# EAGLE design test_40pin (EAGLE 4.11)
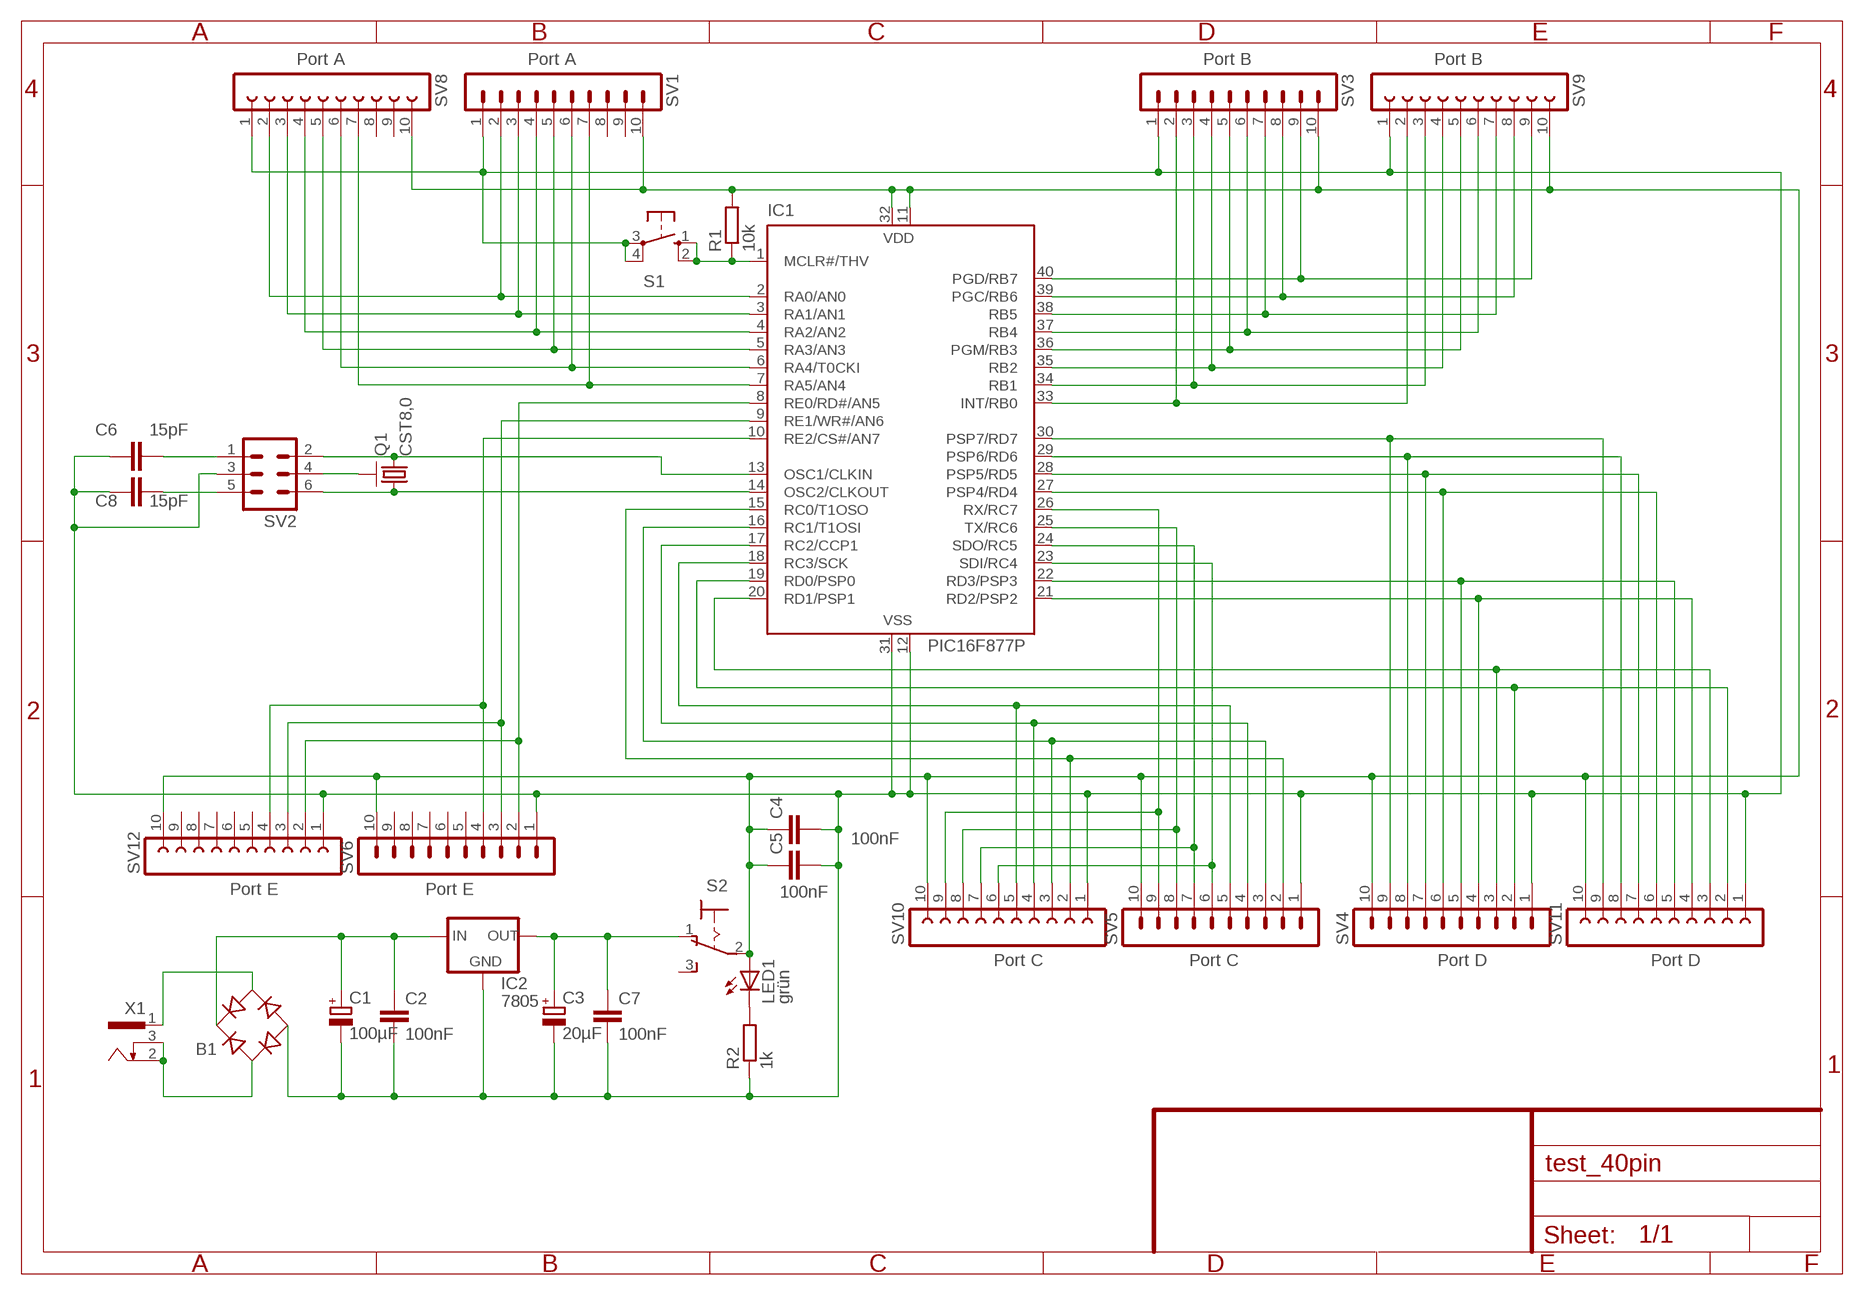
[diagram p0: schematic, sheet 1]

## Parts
B1  RB1A  [RB1A]
C1  100µF  CPOL-EUE5-10.5  [E5-10,5]
C2  100nF  C-EU050-025X075  [C050-025X075]
C3  20µF  CPOL-EUE5-5  [E5-5]
C4  100nF  C-EU050-025X075  [C050-025X075]
C5  100nF  C-EU050-025X075  [C050-025X075]
C6  15pF  C-EU025-025X050  [C025-025X050]
C7  100nF  C-EU050-025X075  [C050-025X075]
C8  15pF  C-EU025-025X050  [C025-025X050]
IC1  PIC16F877P  [DIL40]
IC2  7805  78XXS  [78XXS]
LED1  grün  LED3MM  [LED3MM]
Q1  CST8,0  RESONATOR  [RES3PIN]
R1  10k  R-EU_0207/10  [0207/10]
R2  1k  R-EU_0207/10  [0207/10]
S1  10-XX  [B3F-10XX]
S2  320-916  [320-916]
SV1  Port A  MA10-1  [MA10-1]
SV2  MA03-2  [MA03-2]
SV3  Port B  MA10-1  [MA10-1]
SV4  Port D  MA10-1  [MA10-1]
SV5  Port C  MA10-1  [MA10-1]
SV6  Port E  MA10-1  [MA10-1]
SV8  Port A  FE10W  [FE10W]
SV9  Port B  FE10W  [FE10W]
SV10  Port C  FE10W  [FE10W]
SV11  Port D  FE10W  [FE10W]
SV12  Port E  FE10W  [FE10W]
X1  733989-55  [733989-5]

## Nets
N$1: IC1.2(RA0/AN0) SV1.2 SV8.2
N$2: IC1.3(RA1/AN1) SV1.3 SV8.3
N$3: IC1.4(RA2/AN2) SV1.4 SV8.4
N$4: IC1.5(RA3/AN3) SV1.5 SV8.5
N$5: IC1.6(RA4/T0CKI) SV1.6 SV8.6
N$6: IC1.7(RA5/AN4) SV1.7 SV8.7
N$7: IC1.40(PGD/RB7) SV3.9 SV9.9
N$8: IC1.39(PGC/RB6) SV3.8 SV9.8
N$9: IC1.38(RB5) SV3.7 SV9.7
N$10: IC1.37(RB4) SV3.6 SV9.6
N$11: IC1.36(PGM/RB3) SV3.5 SV9.5
N$12: IC1.35(RB2) SV3.4 SV9.4
N$13: IC1.34(RB1) SV3.3 SV9.3
N$14: IC1.33(INT/RB0) SV3.2 SV9.2
N$15: IC1.26(RX/RC7) SV5.9 SV10.9
N$16: IC1.25(TX/RC6) SV5.8 SV10.8
N$17: IC1.24(SDO/RC5) SV5.7 SV10.7
N$18: IC1.23(SDI/RC4) SV5.6 SV10.6
N$19: IC1.18(RC3/SCK) SV5.5 SV10.5
N$20: IC1.17(RC2/CCP1) SV5.4 SV10.4
N$21: IC1.16(RC1/T1OSI) SV5.3 SV10.3
N$22: IC1.15(RC0/T1OSO) SV5.2 SV10.2
N$23: IC1.30(PSP7/RD7) SV4.9 SV11.9
N$24: IC1.29(PSP6/RD6) SV4.8 SV11.8
N$25: IC1.28(PSP5/RD5) SV4.7 SV11.7
N$26: IC1.27(PSP4/RD4) SV4.6 SV11.6
N$27: IC1.19(RD0/PSP0) SV4.2 SV11.2
N$28: IC1.20(RD1/PSP1) SV4.3 SV11.3
N$29: IC1.21(RD2/PSP2) SV4.4 SV11.4
N$30: IC1.22(RD3/PSP3) SV4.5 SV11.5
N$31: IC1.8(RE0/RD#/AN5) SV6.2 SV12.2
N$32: IC1.9(RE1/WR#/AN6) SV6.3 SV12.3
N$33: IC1.10(RE2/CS#/AN7) SV6.4 SV12.4
N$34: IC1.14(OSC2/CLKOUT) Q1.1 SV2.6
N$35: IC1.1(MCLR#/THV) R1.1 S1.1(S) S1.2(S1)
N$37: C3.+ C7.1 IC2.OUT S2.1(O)
N$38: IC1.13(OSC1/CLKIN) Q1.3 SV2.2
N$39: B1.AC1 X1.2 X1.3
N$40: Q1.2 SV2.4
N$42: B1.+ C1.+ C2.1 IC2.IN
N$43: B1.AC2 X1.1
N$44: C6.2 SV2.1
N$45: C8.2 SV2.5
N$47: LED1.K(C) R2.2
VDD: C4.1 C5.1 IC1.11(VDD) IC1.32(VDD) LED1.A R1.2 S2.2(P) SV1.10 SV3.10 SV4.10 SV5.10 SV6.10 SV8.10 SV9.10 SV10.10 SV11.10 SV12.10
VSS: B1.- C1.- C2.2 C3.- C4.2 C5.2 C6.1 C7.2 C8.1 IC1.12(VSS) IC1.31(VSS) IC2.GND R2.1 S1.3(P) S1.4(P1) SV1.1 SV2.3 SV3.1 SV4.1 SV5.1 SV6.1 SV8.1 SV9.1 SV10.1 SV11.1 SV12.1
Unconnected: S2.3(S) SV1.8 SV1.9 SV6.5 SV6.6 SV6.7 SV6.8 SV6.9 SV8.8 SV8.9 SV12.5 SV12.6 SV12.7 SV12.8 SV12.9

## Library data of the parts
B1 = rectifier:RB1A: RECTIFIER 1 A
C1 C3 = rcl:CPOL-EU: POLARIZED CAPACITOR, European symbol
C2 C4-C8 = rcl:C-EU: CAPACITOR, European symbol
IC1 = microchip:PIC16F87*: MICROCONTROLLER
IC2 = v-reg:78XXS: VOLTAGE REGULATOR
LED1 = led:LED: LED
Q1 = sprut:RESONATOR: CRYSTAL
R1 R2 = rcl:R-EU_: RESISTOR, European symbol
S1 = switch-omron:10-XX: OMRON SWITCH
S2 = switch:320-916: TOGGLE SWITCH distributor RS Components
SV1 SV3-SV6 = con-lstb:MA10-1: PIN HEADER
SV2 = con-lstb:MA03-2: PIN HEADER
SV8-SV12 = con-lsta:FE10W: FEMALE HEADER
X1 = con-conrad:733989-55: FEMALE PRINT CONNECTOR 1.1 mm, FUK HING Industries, distributor Conrad

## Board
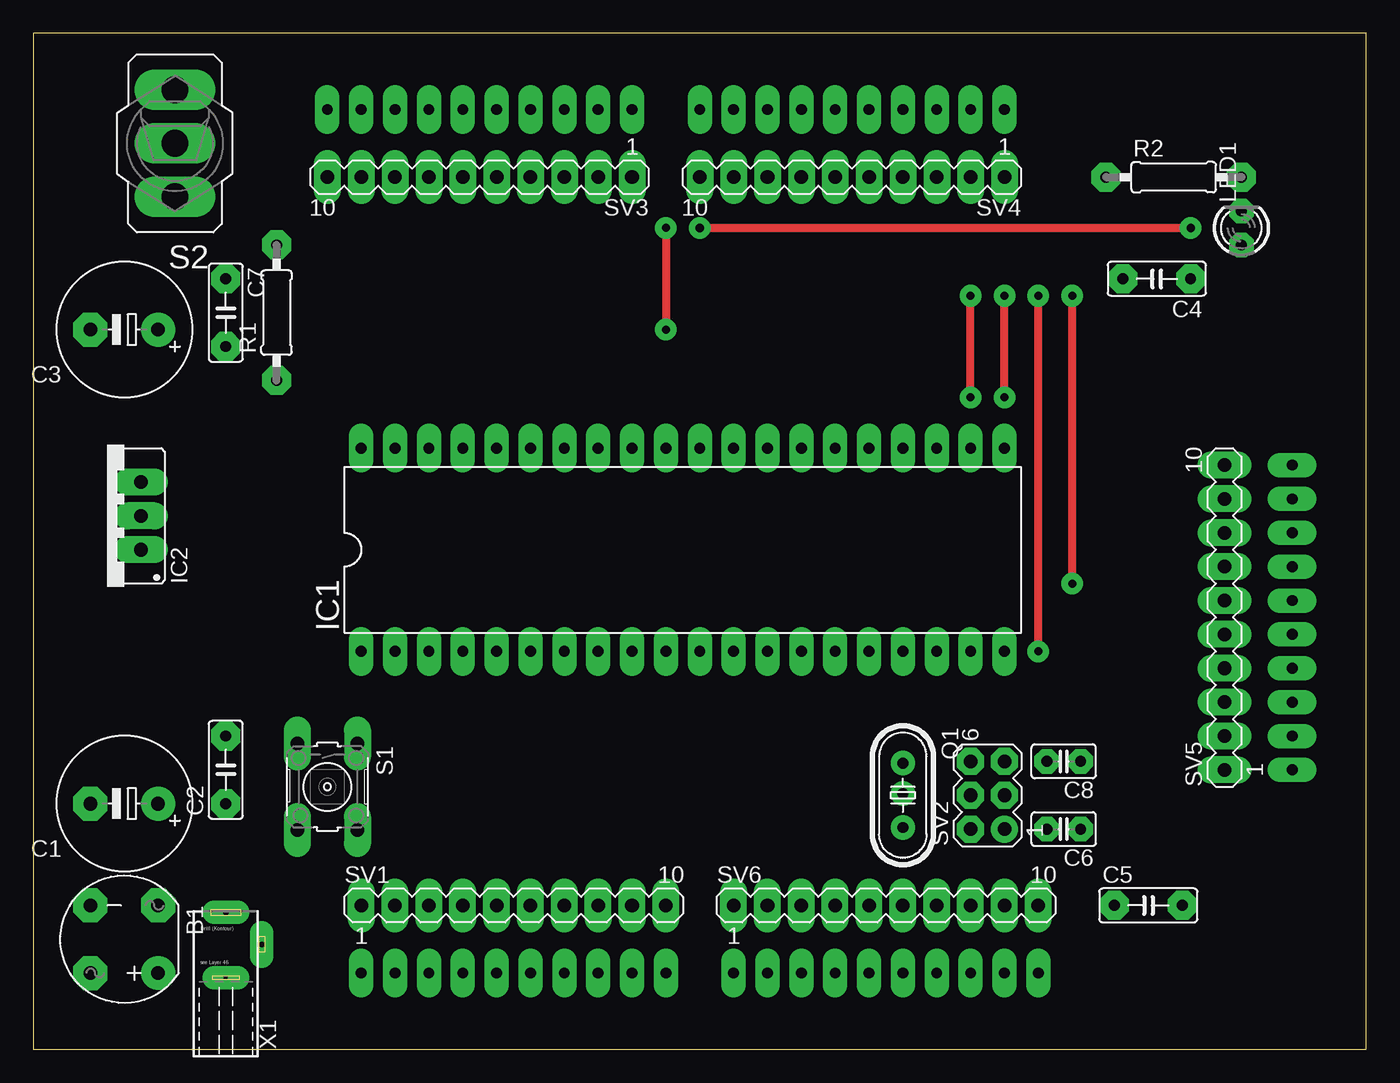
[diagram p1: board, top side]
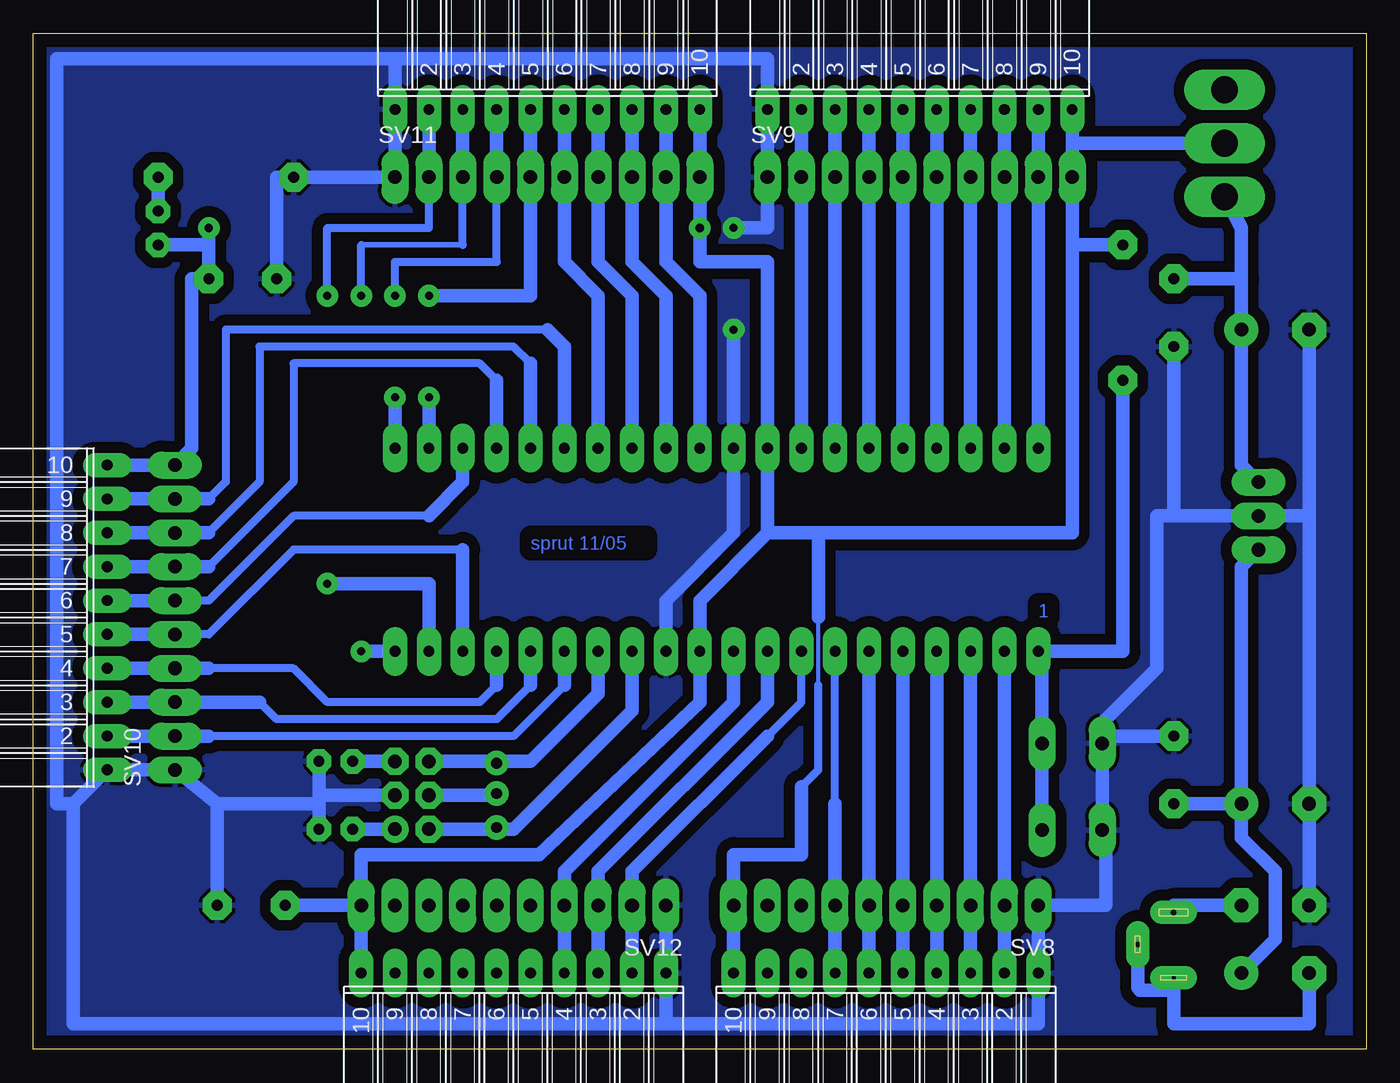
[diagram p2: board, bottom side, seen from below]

Size 100 x 76.19 mm. Coordinates in mm from the lower left corner, seen from the top.
Outline: 0,0 100,0 100,76.19 0,76.19 0,0
Copper layers (1*16): Top 0.035mm / dielectric 1.5mm / Bottom 0.035mm
Design rules "leiterplatte mit löchern": minimum track width 10mil, minimum drill 12mil, track to track 8mil, track to pad 8mil, pad to pad 8mil, via to via 8mil, smd to smd 8mil, copper to edge 40mil, drill to drill 8mil, minimum pad ring 20mil, minimum via ring 20mil, stop-mask expansion 4mil, vias tented up to drill 0mil, thermal gap 10mil

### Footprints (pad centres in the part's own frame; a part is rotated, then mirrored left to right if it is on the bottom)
RB1A = drill 1.016 pad 2.54 round: + -2.54,2.54 | drill 1.016 pad 2.54 octagon: - 2.54,-2.54; AC1 2.54,2.54; AC2 -2.54,-2.54
E5-10,5 = drill 1.016 pad 2.54 round: + -2.54,0 | drill 1.016 pad 2.54 octagon: - 2.54,0
C050-025X075 = drill 0.813 pad 2.184 octagon: 1 -2.54,0; 2 2.54,0
C025-025X050 = drill 0.813 pad 1.778 octagon: 1 -1.27,0; 2 1.27,0
DIL40 = drill 0.813 long: 1 -24.13,-7.62; 2 -21.59,-7.62; 3 -19.05,-7.62; 4 -16.51,-7.62; 5 -13.97,-7.62; 6 -11.43,-7.62; 7 -8.89,-7.62; 8 -6.35,-7.62; 9 -3.81,-7.62; 10 -1.27,-7.62; 11 1.27,-7.62; 12 3.81,-7.62; 13 6.35,-7.62; 14 8.89,-7.62; 15 11.43,-7.62; 16 13.97,-7.62; 17 16.51,-7.62; 18 19.05,-7.62; 19 21.59,-7.62; 20 24.13,-7.62; 21 24.13,7.62; 22 21.59,7.62; 23 19.05,7.62; 24 16.51,7.62; 25 13.97,7.62; 26 11.43,7.62; 27 8.89,7.62; 28 6.35,7.62; 29 3.81,7.62; 30 1.27,7.62; 31 -1.27,7.62; 32 -3.81,7.62; 33 -6.35,7.62; 34 -8.89,7.62; 35 -11.43,7.62; 36 -13.97,7.62; 37 -16.51,7.62; 38 -19.05,7.62; 39 -21.59,7.62; 40 -24.13,7.62
78XXS = drill 1.016 long: GND 0,-2.54; IN -2.54,-2.54; OUT 2.54,-2.54
LED3MM = drill 0.813 octagon: A -1.27,0; K 1.27,0
RES3PIN = drill 0.813 round: 1 -2.413,0; 2 -0.127,0; 3 2.413,0
0207/10 = drill 0.813 pad 2.184 octagon: 1 -5.08,0; 2 5.08,0
B3F-10XX = drill 1.016 long: 1 -3.251,2.261; 2 3.251,2.261; 3 -3.251,-2.261; 4 3.251,-2.261
320-916 = drill 2.007 long: 1 0,4.013; 2 0,0; 3 0,-4.013
MA10-1 = drill 1.016 long: 1 -11.43,0; 2 -8.89,0; 3 -6.35,0; 4 -3.81,0; 5 -1.27,0; 6 1.27,0; 7 3.81,0; 8 6.35,0; 9 8.89,0; 10 11.43,0
MA03-2 = drill 1.016 round: 1 -2.54,-1.27 | drill 1.016 octagon: 2 -2.54,1.27; 3 0,-1.27; 4 0,1.27; 5 2.54,-1.27; 6 2.54,1.27
FE10W = drill 0.813 long: 1 -11.43,0; 2 -8.89,0; 3 -6.35,0; 4 -3.81,0; 5 -1.27,0; 6 1.27,0; 7 3.81,0; 8 6.35,0; 9 8.89,0; 10 11.43,0
733989-5 = drill 0.4 pad 1.778 long: 1 0,5.82; 3 2.7,3.42 | drill 0.3 pad 1.778 long: 2 0,0.92

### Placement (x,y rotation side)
B1  6.82,8.25 180 top
C1  6.82,18.41 180 top
C2  14.44,20.95 90 top
C3  20µF  [E5-10,5]  6.82,53.97 180 top
C4  84.29,57.78 180 top
C5  83.66,10.79 0 top
C6  77.31,16.5 180 top
C7  14.44,55.24 270 top
C8  77.31,21.59 180 top
IC1  48.73,37.46 0 top
IC2  5.55,40 90 top
LED1  90.64,61.59 90 top
Q1  65.24,19.04 270 top
R1  18.25,55.24 90 top
R2  85.56,65.4 0 top
S1  22.06,19.68 270 top
S2  10.63,67.94 180 top
SV1  36.03,10.79 0 top
SV2  71.59,19.04 90 top
SV3  33.49,65.4 180 top
SV4  61.43,65.4 180 top
SV5  89.37,32.38 90 top
SV6  63.97,10.79 0 top
SV8  36.03,5.71 180 bottom
SV9  33.49,70.48 0 bottom
SV10  94.45,32.38 90 bottom
SV11  61.43,70.48 0 bottom
SV12  63.97,5.71 180 bottom
X1  14.44,4.44 0 top

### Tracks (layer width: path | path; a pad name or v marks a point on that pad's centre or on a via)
N$1
  Bottom 1.016: IC1.2 SV1.2 SV8.2
N$2
  Bottom 1.016: IC1.3 SV1.3 SV8.3
N$3
  Bottom 1.016: IC1.4 SV1.4 SV8.4
N$4
  Bottom 1.016: IC1.5 SV1.5 SV8.5
N$5
  Bottom 1.016: IC1.6 SV1.6 SV8.6
N$6
  Bottom 0.61: 39.84,18.41 IC1.7
  Bottom 1.016: 39.84,18.41 SV1.7 SV8.7
N$7
  Bottom 1.016: IC1.40 SV3.9 SV9.9
N$8
  Bottom 1.016: IC1.39 SV3.8 SV9.8
N$9
  Bottom 1.016: IC1.38 SV3.7 SV9.7
N$10
  Bottom 1.016: IC1.37 SV3.6 SV9.6
N$11
  Bottom 1.016: IC1.36 SV3.5 SV9.5
N$12
  Bottom 1.016: IC1.35 SV3.4 SV9.4
N$13
  Bottom 1.016: IC1.34 SV3.3 SV9.3
N$14
  Bottom 1.016: IC1.33 SV3.2 SV9.2
N$15
  Bottom 0.61: 86.83,41.27 85.56,42.54 85.56,53.97 61.43,53.97
  Bottom 1.016: 86.83,41.27 SV5.9 SV10.9 | 61.43,53.97 60.16,52.7 IC1.26
N$16
  Bottom 0.61: 86.83,38.73 83.02,42.54 83.02,52.7 63.97,52.7 62.7,51.43
  Bottom 1.016: 86.83,38.73 SV5.8 SV10.8 | IC1.25 62.7,51.43
N$17
  Bottom 0.61: 86.83,36.19 80.48,42.54 80.48,51.43 66.51,51.43 65.24,50.16
  Bottom 1.016: 86.83,36.19 SV5.7 SV10.7 | IC1.24 65.24,50.16
N$18
  Bottom 0.61: SV5.6 86.83,33.65 80.48,40 70.32,40
  Bottom 1.016: 70.32,40 67.78,42.54 IC1.23 | SV5.6 SV10.6
N$19
  Bottom 0.61: 67.78,37.46 80.48,37.46 86.83,31.11 SV5.5
  Bottom 1.016: SV5.5 SV10.5 | IC1.18 67.78,37.46
N$20
  Bottom 0.61: 65.24,27.3 66.51,26.03 77.94,26.03 80.48,28.57 86.83,28.57
  Bottom 1.016: 65.24,27.3 IC1.17 | 86.83,28.57 SV5.4 SV10.4
N$21
  Bottom 0.61: 62.7,27.3 65.24,24.76 81.75,24.76 83.02,26.03
  Bottom 1.016: 62.7,27.3 IC1.16 | 83.02,26.03 SV5.3 SV10.3
N$22
  Bottom 0.61: 60.16,27.3 63.97,23.49 86.83,23.49
  Bottom 1.016: 60.16,27.3 IC1.15 | 86.83,23.49 SV5.2 SV10.2
N$23
  Bottom 1.016: IC1.30 50,56.51 52.54,59.05 SV4.9 SV11.9
N$24
  Bottom 1.016: IC1.29 52.54,56.51 55.08,59.05 SV4.8 SV11.8
N$25
  Bottom 1.016: IC1.28 55.08,56.51 57.62,59.05 SV4.7 SV11.7
N$26
  Bottom 1.016: IC1.27 57.62,56.51 60.16,59.05 SV4.6 SV11.6
N$27  (via drill 0.6)
  Top 0.61: v77.94,34.92 v77.94,56.51
  Bottom 0.61: SV4.2 70.32,61.59 77.94,61.59 v77.94,56.51
  Bottom 1.016: v77.94,34.92 70.32,34.92 IC1.19 | SV4.2 SV11.2
N$28  (via drill 0.6)
  Top 0.61: v75.4,29.84 v75.4,56.51
  Bottom 0.406: 75.4,60.32 67.78,60.32
  Bottom 0.61: 67.78,60.32 SV4.3 | v75.4,56.51 75.4,60.32
  Bottom 1.016: IC1.20 v75.4,29.84 | SV4.3 SV11.3
N$29  (via drill 0.6)
  Top 0.61: v72.86,48.89 v72.86,56.51
  Bottom 0.61: v72.86,56.51 72.86,59.05 65.24,59.05 SV4.4
  Bottom 1.016: IC1.21 v72.86,48.89 | SV4.4 SV11.4
N$30  (via drill 0.6)
  Top 0.61: v70.32,48.89 v70.32,56.51
  Bottom 1.016: v70.32,56.51 62.7,56.51 SV4.5 SV11.5 | IC1.22 v70.32,48.89
N$31
  Bottom 0.61: IC1.8 42.38,26.03 44.92,23.49
  Bottom 1.016: 44.92,23.49 55.08,13.33 SV6.2 SV12.2
N$32
  Bottom 1.016: IC1.9 44.92,26.03 57.62,13.33 SV6.3 SV12.3
N$33
  Bottom 1.016: IC1.10 47.46,26.03 60.16,13.33 SV6.4 SV12.4
N$34
  Bottom 0.406: 63.97,21.59 Q1.1
  Bottom 1.016: IC1.14 57.62,26.66 62.7,21.59 63.97,21.59 SV2.6
N$35
  Bottom 0.406: 24.32,29.56 IC1.1 | S1.1 24.52,22.93 24.6,22.86 24.6,22.22
  Bottom 1.016: S1.2 24.32,21.94 24.6,22.22 | S1.1 24.32,29.56 | R1.1 18.25,29.84 IC1.1
N$37
  Bottom 0.406: 10.63,64.13 S2.1
  Bottom 1.016: C3.+ 9.36,61.59 10.63,64.13 | IC2.OUT 9.36,43.81 C3.+ | C3.+ 9.36,57.78 C7.1
N$38
  Bottom 0.406: 63.97,16.5 Q1.3
  Bottom 1.016: IC1.13 55.08,25.39 63.97,16.5 SV2.2
N$39
  Bottom 0.406: 16.98,4.44 17.14,4.6
  Bottom 1.016: B1.AC1 4.28,1.9 14.44,1.9 14.44,4.44 | 14.44,4.44 X1.2 | 17.14,4.6 X1.3 | 14.44,4.44 16.98,4.44
N$40
  Bottom 1.016: Q1.2 65.24,19.04 SV2.4
N$42
  Bottom 1.016: IC2.IN 9.36,36.19 C1.+ | C1.+ C2.1 | B1.+ 6.82,8.25 6.82,13.33 9.36,15.87 C1.+
N$43
  Bottom 1.016: B1.AC2 14.44,10.79 X1.1
N$44
  Bottom 1.016: SV2.1 C6.2
N$45
  Bottom 1.016: SV2.5 C8.2
N$47
  Bottom 1.016: LED1.K R2.2
VDD  (via drill 0.61)
  Top 0.61: v50,61.59 v86.83,61.59
  Bottom 0.305: 41.11,27.3 41.11,32.38
  Bottom 0.61: 42.38,19.68 41.11,20.95 41.11,27.3
  Bottom 1.016: 44.92,38.73 IC1.32 44.92,59.05 50,59.05 v50,61.59 SV4.10 SV11.10 | 44.92,38.73 50,33.65 IC1.11 50,26.03 62.07,14.6 75.4,14.6 SV6.10 | 42.38,19.68 42.38,14.6 47.46,14.6 SV1.10 SV8.10 | 41.11,32.38 41.11,38.73 | 41.11,38.73 44.92,38.73 | 22.06,60.32 22.06,38.73 41.11,38.73 | 22.06,60.32 SV3.10 SV9.10 22.06,67.94 S2.2 | 22.06,60.32 R1.2 | SV6.10 SV12.10 | SV10.10 SV5.10 88.1,45.08 88.1,57.78 C4.1 v86.83,61.59 86.83,60.32 LED1.A | SV6.10 C5.1
VSS  (via drill 0.6)
  Top 0.61: v47.46,61.59 v47.46,53.97
  Bottom 0.406: S1.4 19.8,15.87 19.52,15.87 | 19.52,15.87 19.8,16.15 | SV12.1 SV6.1 | SV4.1 SV11.1 | 19.52,23.49 19.52,15.87
  Bottom 1.016: IC1.12 52.54,33.65 47.46,38.73 IC1.31 v47.46,53.97 | v47.46,61.59 44.92,61.59 SV3.1 SV9.1 44.92,74.29 72.86,74.29 | 19.8,16.15 S1.3 | 52.54,1.9 24.6,1.9 SV8.1 SV1.1 19.52,10.79 19.52,15.87 | 72.86,74.29 SV4.1 R2.1 81.75,65.4 C4.2 | SV12.1 SV6.1 SV12.1 | 96.99,18.41 SV10.1 SV5.1 86.2,18.41 | 4.28,40 IC2.GND 14.44,40 | 14.44,40 15.71,40 15.71,28.57 19.52,24.76 19.52,23.49 C2.2 | B1.- C1.- 4.28,40 | 4.28,40 C3.- | 14.44,40 C7.2 | 78.58,18.41 78.58,19.04 | 78.58,19.04 C8.1 | 78.58,19.04 SV2.3 | 86.2,18.41 78.58,18.41 | 78.58,18.41 C6.1 | 86.2,18.41 C5.2 | 52.54,1.9 SV12.1 | 52.54,1.9 96.99,1.9 96.99,18.41 | 96.99,18.41 98.26,18.41 98.26,74.29 72.86,74.29
  pour Bottom (isolate 0.813): -0.8,-0.64 -0.8,76.83 100.8,76.83 100.8,-0.64

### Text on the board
Bottom: sprut 11/05 | 1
